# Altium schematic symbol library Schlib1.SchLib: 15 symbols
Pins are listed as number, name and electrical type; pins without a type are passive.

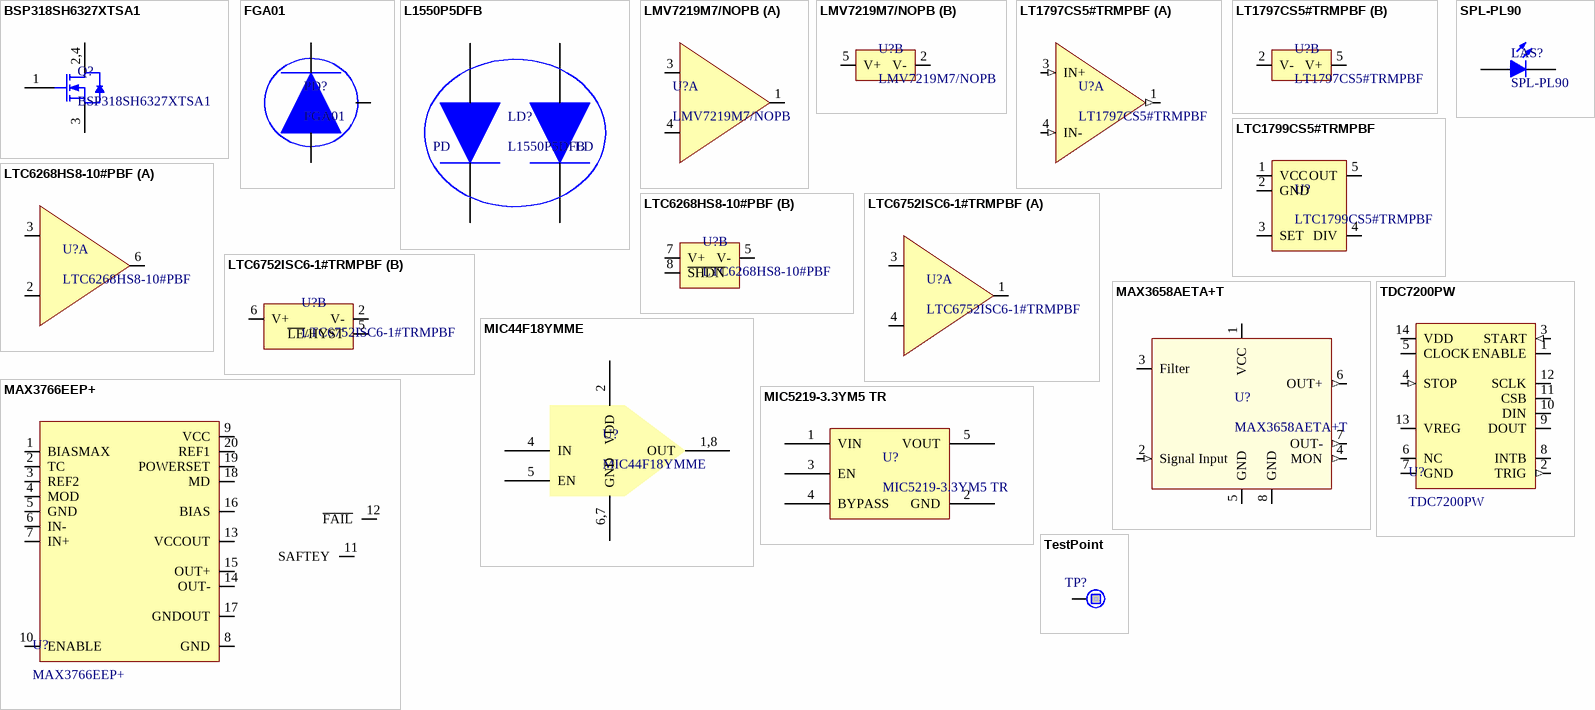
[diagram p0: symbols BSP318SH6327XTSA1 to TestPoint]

## BSP318SH6327XTSA1
designator Q?
MOSFET N-Ch 60V 2.6A SOT-223-3
pins: 1 G, 2 D, 3 S, 4 D

## FGA01
designator PD?
InGaAs Photodiode, 300 ps Rise Time, 800-1700 nm, Ø0.12 mm Active Area
pins: 1 CATHODE, 2 CASE, 3 ANODE

## L1550P5DFB
designator LD?
1550 nm, 5 mW, Ø5.6 mm, D Pin Code, DFB Laser Diode with Aspheric Lens Cap
pins: 1 CATHODE, 2 ANODE, 3 ANODE, 4 CATHODE

## LMV7219M7/NOPB
designator U?
IC COMPARATOR SC-70-5
part A pins: 1 OUT, 3 IN+, 4 IN-
part B pins: 2 V-, 5 V+

## LT1797CS5#TRMPBF
designator U?
IC OPAMP BUFFER 11MHZ TSOT23-5
footprint LT1797CS5#TRMPBF--SOT95P280X100-5N (SOT23, 5-Leads, Body 2.90x2.80mm, Pitch 0.95mm, IPC Medium Density)
part A pins: 1 OUT (out), 3 IN+ (in), 4 IN- (in)
part B pins: 2 V- (power), 5 V+ (power)

## LTC1799CS5#TRMPBF
designator U?
IC OSC SILICON PROG TSOT23-5
pins: 1 VCC, 2 GND, 3 SET, 4 DIV, 5 OUT

## LTC6268HS8-10#PBF
designator U?
IC OPAMP 4GHZ SGL FET 8SOIC
part A pins: 2 IN-, 3 IN+, 6 OUT
part B pins: 5 V-, 7 V+, 8 ~{SHDN}

## LTC6752ISC6-1#TRMPBF
designator U?
IC COMP R-R CMOS 280MHZ SC70-6
part A pins: 1 OUT, 3 IN+, 4 IN-
part B pins: 2 V-, 5 ~{LE}/HYST, 6 V+

## MAX3658AETA+T
designator U?
IC AMP TRANSIMPEDANCE 8-TDFN
pins: 1 VCC (power), 2 Signal Input (in), 3 Filter , 4 MON (out) "Optional Photocurrent Monitor. This is a current output. Connect a resistor between MON and ground  to monitor the average photocurrent. Leave this pin open if a monitor is not required.", 5 GND (power), 6 OUT+ (out), 7 OUT- (out), 8 GND (power), 9 PAD hidden to GND, 9 GND (power) hidden to GND

## MAX3766EEP+
designator U?
IC LASR DRVR 622MBPS 5.5V 20QSOP
footprint MAX3766EEP+--SOP64P600X173-20N (SOP, 20-Leads, Body 8.65x3.90mm, Pitch 0.64mm, IPC Medium Density)
pins: 1 BIASMAX, 2 TC, 3 REF2, 4 MOD, 5 GND, 6 IN-, 7 IN+, 8 GND, 9 VCC, 10 ENABLE, 11 SAFTEY, 12 ~{FAIL}, 13 VCCOUT, 14 OUT-, 15 OUT+, 16 BIAS, 17 GNDOUT, 18 MD, 19 POWERSET, 20 REF1

## MIC44F18YMME
designator U?
Gate Drivers 3A High Speed MOSFET Driver
pins: 1 OUT, 2 VDD, 3 NC hidden, 4 IN, 5 EN, 6 GND, 7 GND, 8 OUT

## MIC5219-3.3YM5 TR
designator U?
IC REG LDO 3.3V 0.5A SOT23-5
pins: 1 VIN, 2 GND, 3 EN, 4 BYPASS, 5 VOUT

## SPL-PL90
designator LAS?
footprint SPL-PL90
pins: 1 A, 2 K

## TDC7200PW
designator U?
STATIC ULTRASONIC FLOWMETER AF
pins: 1 ENABLE, 2 TRIG (out), 3 START (in), 4 STOP (in), 5 CLOCK, 6 NC, 7 GND, 8 INTB, 9 DOUT, 10 DIN, 11 CSB, 12 SCLK, 13 VREG, 14 VDD

## TestPoint
designator TP?  (value not drawn)
footprint TestPoint
pins: 1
